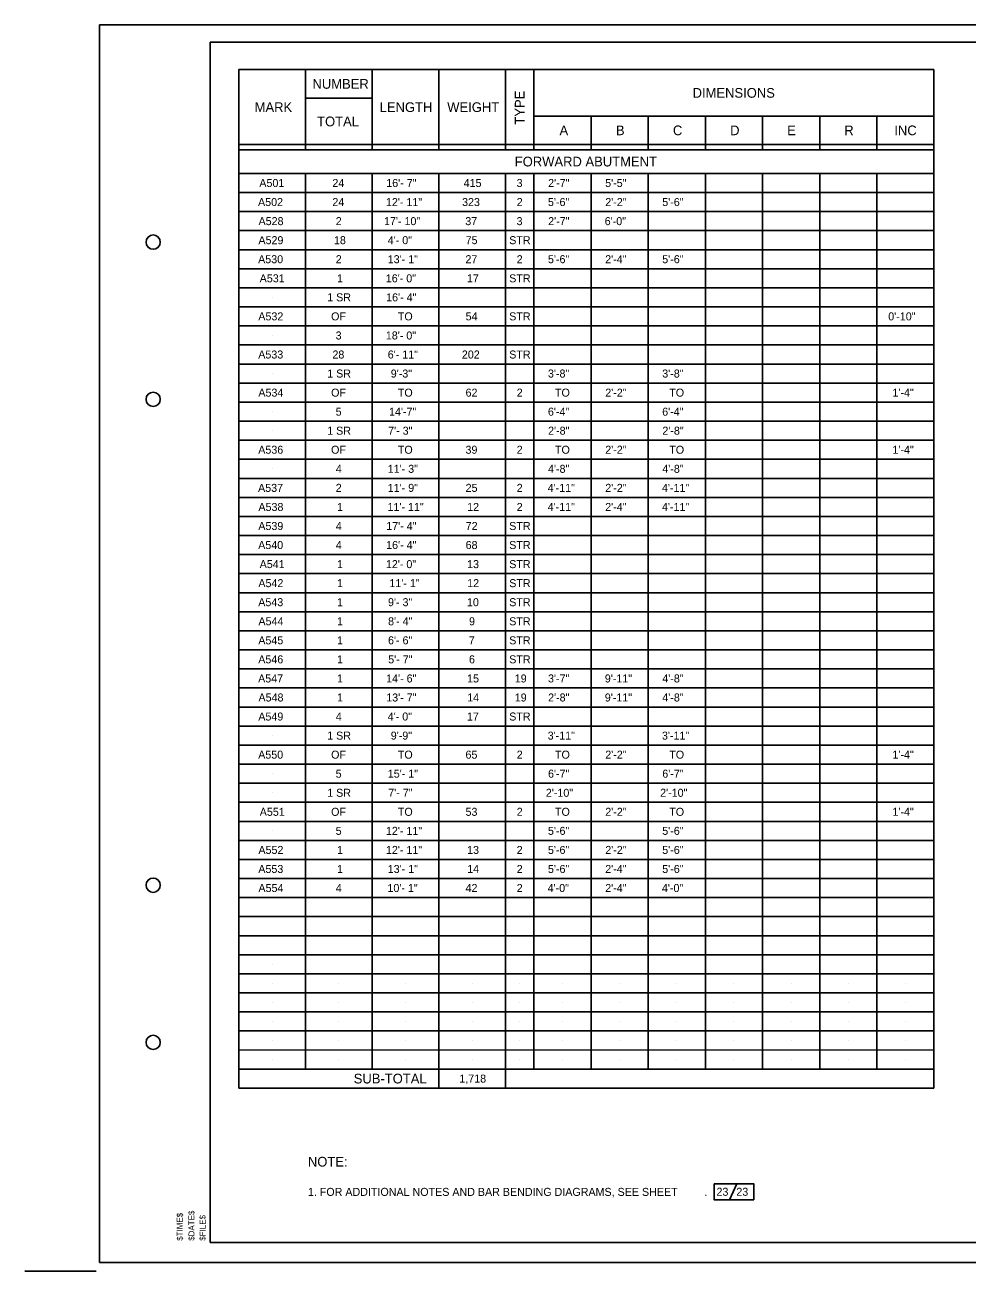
# Model space of a CAD drawing. Extents: x -9.2 to 26.7, y -24.6 to -2.6.
# Drawn here: x -9.21 to 7.28, y -24.61 to -2.81 of the extents above; entities that cross this region are included whole.
import ezdxf

# ---------------------------------------------------------------- set-up
doc = ezdxf.new("R2010")
doc.units = 0
for name, color, linetype in [('BR_P_Gen_Text', 7, 'Continuous'), ('Default', 7, 'Continuous'), ('SC_Scratch1', 7, 'Continuous'), ('SH_Border', 7, 'Continuous'), ('SH_Cut_Line', 7, 'Continuous'), ('TX_P_1', 7, 'Continuous')]:
    doc.layers.add(name, color=color, linetype=linetype)

msp = doc.modelspace()

# ---------------------------------------------------------------- linework, layer by layer
at = {"layer": 'BR_P_Gen_Text'}
for p, q in [((-5.469, -3.594), (6.697, -3.594)), ((-5.469, -21.411), (-5.469, -3.594)), ((-4.302, -4.995), (-4.302, -3.594)), ((-3.135, -4.995), (-3.135, -3.595)), ((-1.969, -4.995), (-1.969, -3.594)), ((-0.802, -4.995), (-0.802, -3.595)), ((-0.302, -4.995), (-0.302, -3.595)), ((6.697, -21.411), (6.697, -3.594)), ((-4.302, -4.094), (-3.135, -4.094)), ((-0.302, -4.407), (6.697, -4.407)), ((0.698, -4.995), (0.698, -4.407)), ((1.698, -4.995), (1.698, -4.407)), ((2.698, -4.995), (2.698, -4.407)), ((3.698, -4.995), (3.698, -4.407)), ((4.698, -4.995), (4.698, -4.407)), ((5.697, -4.995), (5.698, -4.407)), ((-5.469, -4.907), (6.697, -4.907)), ((-5.469, -4.995), (6.697, -4.995)), ((-5.469, -5.411), (6.697, -5.411)), ((-5.469, -5.411), (6.697, -5.411)), ((-4.302, -21.078), (-4.302, -5.411)), ((-3.135, -21.078), (-3.135, -5.411)), ((-1.969, -21.411), (-1.969, -5.411)), ((-0.802, -21.411), (-0.802, -5.411)), ((-0.302, -21.078), (-0.302, -5.411)), ((0.698, -21.078), (0.698, -5.411)), ((1.698, -21.078), (1.698, -5.411)), ((2.698, -21.078), (2.698, -5.411)), ((3.698, -21.078), (3.698, -5.411)), ((4.698, -21.078), (4.698, -5.411)), ((5.698, -21.078), (5.698, -5.411)), ((-5.469, -5.745), (6.697, -5.745)), ((-5.469, -6.078), (6.697, -6.078)), ((-5.469, -6.411), (6.697, -6.411)), ((-5.469, -6.745), (6.697, -6.745)), ((-5.469, -7.078), (6.697, -7.078)), ((-5.469, -7.411), (6.697, -7.411)), ((-5.469, -7.745), (6.697, -7.745)), ((-5.469, -8.078), (6.697, -8.078)), ((-5.469, -8.411), (6.697, -8.411)), ((-5.469, -8.745), (6.697, -8.745)), ((-5.469, -9.078), (6.697, -9.078)), ((-5.469, -9.411), (6.697, -9.411)), ((-5.469, -9.745), (6.697, -9.745)), ((-5.469, -10.078), (6.697, -10.078)), ((-5.469, -10.411), (6.697, -10.411)), ((-5.469, -10.745), (6.697, -10.745)), ((-5.469, -11.078), (6.697, -11.078)), ((-5.469, -11.411), (6.697, -11.411)), ((-5.469, -11.745), (6.697, -11.745)), ((-5.469, -12.078), (6.697, -12.078)), ((-5.469, -12.411), (6.697, -12.411)), ((-5.469, -12.745), (6.697, -12.745)), ((-5.469, -13.078), (6.697, -13.078)), ((-5.469, -13.411), (6.697, -13.411)), ((-5.469, -13.745), (6.697, -13.745)), ((-5.469, -14.078), (6.697, -14.078)), ((-5.469, -14.411), (6.697, -14.411)), ((-5.469, -14.745), (6.697, -14.745)), ((-5.469, -15.078), (6.697, -15.078)), ((-5.469, -15.411), (6.697, -15.411)), ((-5.469, -15.745), (6.697, -15.745)), ((-5.469, -16.078), (6.697, -16.078)), ((-5.469, -16.411), (6.697, -16.411)), ((-5.469, -16.745), (6.697, -16.745)), ((-5.469, -17.078), (6.697, -17.078)), ((-5.469, -17.411), (6.697, -17.411)), ((-5.469, -17.745), (6.697, -17.745)), ((-5.469, -18.078), (6.697, -18.078)), ((-5.469, -18.411), (6.697, -18.411)), ((-5.469, -18.745), (6.697, -18.745)), ((-5.469, -19.078), (6.697, -19.078)), ((-5.469, -19.411), (6.697, -19.411)), ((-5.469, -19.745), (6.697, -19.745)), ((-5.469, -20.078), (6.697, -20.078)), ((-5.469, -20.411), (6.697, -20.411)), ((-5.469, -20.745), (6.697, -20.744)), ((-5.469, -21.078), (6.697, -21.078)), ((-5.469, -21.411), (6.697, -21.411)), ((-5.469, -21.411), (6.697, -21.411))]:
    msp.add_line(p, q, dxfattribs=at)
at = {"layer": 'SC_Scratch1'}
for p, q in [((0.614, -5.203), (0.614, -5.203)), ((-4.885, -5.578), (-4.885, -5.578)), ((-4.885, -5.911), (-4.885, -5.911)), ((-4.885, -6.245), (-4.885, -6.245)), ((-4.885, -6.578), (-4.885, -6.578)), ((-4.885, -6.911), (-4.885, -6.911)), ((-4.885, -7.245), (-4.885, -7.245)), ((-4.885, -7.578), (-4.885, -7.578)), ((-4.885, -7.911), (-4.885, -7.911)), ((-4.885, -8.245), (-4.885, -8.245)), ((-4.885, -8.578), (-4.885, -8.578)), ((-4.885, -8.911), (-4.885, -8.911)), ((-4.885, -9.245), (-4.885, -9.245)), ((-4.885, -9.578), (-4.885, -9.578)), ((-4.885, -9.911), (-4.885, -9.911)), ((-4.885, -9.911), (-4.885, -9.911)), ((-4.885, -10.245), (-4.885, -10.245)), ((-4.885, -10.245), (-4.885, -10.245)), ((-4.885, -10.578), (-4.885, -10.578)), ((-4.885, -10.578), (-4.885, -10.578)), ((-4.885, -10.911), (-4.885, -10.911)), ((-4.885, -11.245), (-4.885, -11.245)), ((-4.885, -11.578), (-4.885, -11.578)), ((-4.885, -11.911), (-4.885, -11.911)), ((-4.885, -12.245), (-4.885, -12.245)), ((-4.885, -12.578), (-4.885, -12.578)), ((-4.885, -12.911), (-4.885, -12.911)), ((-4.885, -13.245), (-4.885, -13.245)), ((-4.885, -13.578), (-4.885, -13.578)), ((-4.885, -13.911), (-4.885, -13.911)), ((-4.885, -14.245), (-4.885, -14.245)), ((-4.885, -14.578), (-4.885, -14.578)), ((-4.885, -14.911), (-4.885, -14.911)), ((-4.885, -15.245), (-4.885, -15.245)), ((-4.885, -15.578), (-4.885, -15.578)), ((-4.885, -15.911), (-4.885, -15.911)), ((-4.885, -16.245), (-4.885, -16.245)), ((-4.885, -16.578), (-4.885, -16.578)), ((-4.885, -16.911), (-4.885, -16.911)), ((-4.885, -17.245), (-4.885, -17.245)), ((-4.885, -17.578), (-4.885, -17.578)), ((-4.885, -17.911), (-4.885, -17.911)), ((-4.885, -19.245), (-4.885, -19.245)), ((-4.885, -19.578), (-4.885, -19.578)), ((-4.885, -19.578), (-4.885, -19.578)), ((-3.719, -19.578), (-3.719, -19.578)), ((-2.552, -19.578), (-2.552, -19.578)), ((-1.385, -19.578), (-1.385, -19.578)), ((-0.552, -19.578), (-0.552, -19.578)), ((0.198, -19.578), (0.198, -19.578)), ((1.198, -19.578), (1.198, -19.578)), ((2.198, -19.578), (2.198, -19.578)), ((3.198, -19.578), (3.198, -19.578)), ((4.198, -19.578), (4.198, -19.578)), ((5.198, -19.578), (5.198, -19.578)), ((6.198, -19.578), (6.198, -19.578)), ((-4.885, -19.911), (-4.885, -19.911)), ((-3.719, -19.911), (-3.719, -19.911)), ((-2.552, -19.911), (-2.552, -19.911)), ((-1.385, -19.911), (-1.385, -19.911)), ((-0.552, -19.911), (-0.552, -19.911)), ((0.198, -19.911), (0.198, -19.911)), ((1.198, -19.911), (1.198, -19.911)), ((2.198, -19.911), (2.198, -19.911)), ((3.198, -19.911), (3.198, -19.911)), ((4.198, -19.911), (4.198, -19.911)), ((5.198, -19.911), (5.198, -19.911)), ((6.197, -19.911), (6.197, -19.911)), ((-4.885, -20.245), (-4.885, -20.245)), ((-3.719, -20.245), (-3.719, -20.245)), ((-2.552, -20.245), (-2.552, -20.245)), ((-1.385, -20.245), (-1.385, -20.245)), ((-0.552, -20.245), (-0.552, -20.245)), ((0.198, -20.245), (0.198, -20.245)), ((1.198, -20.245), (1.198, -20.245)), ((2.198, -20.245), (2.198, -20.245)), ((3.198, -20.245), (3.198, -20.245)), ((4.197, -20.245), (4.197, -20.245)), ((5.197, -20.245), (5.197, -20.245)), ((6.197, -20.245), (6.197, -20.245)), ((-4.885, -20.578), (-4.885, -20.578)), ((-3.719, -20.578), (-3.719, -20.578)), ((-2.552, -20.578), (-2.552, -20.578)), ((-1.386, -20.578), (-1.386, -20.578)), ((-0.552, -20.578), (-0.552, -20.578)), ((0.198, -20.578), (0.198, -20.578)), ((1.198, -20.578), (1.198, -20.578)), ((2.198, -20.578), (2.198, -20.578)), ((3.197, -20.578), (3.197, -20.578)), ((4.197, -20.578), (4.197, -20.578)), ((5.197, -20.578), (5.197, -20.578)), ((6.197, -20.578), (6.197, -20.578)), ((-4.885, -20.911), (-4.885, -20.911)), ((-3.719, -20.911), (-3.719, -20.911)), ((-2.552, -20.911), (-2.552, -20.911)), ((-1.385, -20.911), (-1.385, -20.911)), ((-0.552, -20.911), (-0.552, -20.911)), ((0.198, -20.911), (0.198, -20.911)), ((1.198, -20.911), (1.198, -20.911)), ((2.198, -20.911), (2.198, -20.911)), ((3.198, -20.911), (3.198, -20.911)), ((4.198, -20.911), (4.198, -20.911)), ((5.198, -20.911), (5.198, -20.911)), ((6.198, -20.911), (6.198, -20.911)), ((-2.552, -21.245), (-2.552, -21.245)), ((-1.386, -21.245), (-1.386, -21.245))]:
    msp.add_line(p, q, dxfattribs=at)
at = {"layer": 'SH_Border'}
msp.add_lwpolyline([(-5.966, -3.112), (25.534, -3.112), (25.534, -24.112), (-5.966, -24.112)], close=True, dxfattribs=at)
for centre in [(-6.966, -6.612), (-6.966, -9.362), (-6.966, -17.862), (-6.966, -20.612)]:
    msp.add_circle(centre, 0.125, dxfattribs=at)
at = {"layer": 'SH_Cut_Line'}
msp.add_line((-7.966, -24.612), (-9.21, -24.612), dxfattribs=at)
msp.add_lwpolyline([(26.096, -24.462), (-7.904, -24.462), (-7.904, -2.812), (26.096, -2.812)], close=True, dxfattribs=at)
at = {"layer": 'TX_P_1'}
msp.add_line((3.246, -23.086), (3.117, -23.364), dxfattribs=at)
msp.add_lwpolyline([(2.849, -23.086), (3.545, -23.086), (3.545, -23.364), (2.849, -23.364)], close=True, dxfattribs=at)
msp.add_lwpolyline([(2.849, -23.086), (3.545, -23.086), (3.545, -23.364), (2.849, -23.364)], close=True, dxfattribs=at)

# ---------------------------------------------------------------- texts
at = {"layer": 'BR_P_Gen_Text'}
for s, p in [('A501', (-5.108, -5.648)), ('24', (-3.83, -5.648)), (' 16\'- 7"', (-2.939, -5.648)), ('415', (-1.533, -5.648)), ('3', (-0.606, -5.648)), ('2\'-7"', (-0.054, -5.648)), ('5\'-5"', (0.944, -5.648)), ('A502', (-5.131, -5.981)), ('24', (-3.83, -5.981)), (' 12\'- 11"', (-2.944, -5.981)), ('323', (-1.56, -5.981)), ('2', (-0.604, -5.981)), ('5\'-6"', (-0.057, -5.981)), ('2\'-2"', (0.946, -5.981)), ('5\'-6"', (1.943, -5.981)), ('A528', (-5.122, -6.315)), ('2', (-3.771, -6.315)), (' 17\'- 10"', (-2.978, -6.315)), ('37', (-1.504, -6.315)), ('3', (-0.606, -6.315)), ('2\'-7"', (-0.054, -6.315)), ('6\'-0"', (0.936, -6.315)), ('A529', (-5.124, -6.648)), ('18', (-3.802, -6.648)), (' 4\'- 0"', (-2.913, -6.648)), ('75', (-1.498, -6.648)), ('STR', (-0.735, -6.648)), ('A530', (-5.129, -6.981)), ('2', (-3.771, -6.981)), (' 13\'- 1"', (-2.913, -6.981)), ('27', (-1.501, -6.981)), ('2', (-0.604, -6.981)), ('5\'-6"', (-0.057, -6.981)), ('2\'-4"', (0.945, -6.981)), ('5\'-6"', (1.943, -6.981)), ('A531', (-5.102, -7.315)), ('1', (-3.748, -7.315)), (' 16\'- 0"', (-2.947, -7.315)), ('17', (-1.475, -7.315)), ('STR', (-0.735, -7.315)), ('1 SR', (-3.92, -7.648)), (' 16\'- 4"', (-2.941, -7.648)), ('A532', (-5.126, -7.981)), ('OF', (-3.852, -7.981)), ('TO', (-2.684, -7.981)), ('54', (-1.498, -7.981)), ('STR', (-0.735, -7.981)), ('0\'-10"', (5.898, -7.981)), ('3', (-3.773, -8.315)), (' 18\'- 0"', (-2.946, -8.315)), ('A533', (-5.127, -8.648)), ('28', (-3.829, -8.648)), (' 6\'- 11"', (-2.913, -8.648)), ('202', (-1.564, -8.648)), ('STR', (-0.735, -8.648)), ('1 SR', (-3.92, -8.981)), ('9\'-3"', (-2.808, -8.981)), ('3\'-8"', (-0.057, -8.981)), ('3\'-8"', (1.943, -8.981)), ('A534', (-5.125, -9.315)), ('OF', (-3.852, -9.315)), ('TO', (-2.684, -9.315)), ('62', (-1.499, -9.315)), ('2', (-0.604, -9.315)), ('TO', (0.066, -9.315)), ('2\'-2"', (0.946, -9.315)), ('TO', (2.066, -9.315)), ('1\'-4"', (5.971, -9.315)), ('5', (-3.772, -9.648)), ('14\'-7"', (-2.838, -9.648)), ('6\'-4"', (-0.058, -9.648)), ('6\'-4"', (1.942, -9.648)), ('1 SR', (-3.92, -9.981)), (' 7\'- 3"', (-2.906, -9.981)), ('2\'-8"', (-0.055, -9.981)), ('2\'-8"', (1.945, -9.981)), ('A536', (-5.127, -10.314)), ('OF', (-3.852, -10.314)), ('TO', (-2.684, -10.314)), ('39', (-1.5, -10.314)), ('2', (-0.604, -10.314)), ('TO', (0.066, -10.314)), ('2\'-2"', (0.946, -10.314)), ('TO', (2.066, -10.314)), ('1\'-4"', (5.971, -10.314)), ('4', (-3.77, -10.648)), (' 11\'- 3"', (-2.913, -10.648)), ('4\'-8"', (-0.056, -10.648)), ('4\'-8"', (1.944, -10.648)), ('A537', (-5.13, -10.981)), ('2', (-3.771, -10.981)), (' 11\'- 9"', (-2.913, -10.981)), ('25', (-1.498, -10.981)), ('2', (-0.604, -10.981)), ('4\'-11"', (-0.062, -10.981)), ('2\'-2"', (0.946, -10.981)), ('4\'-11"', (1.938, -10.981)), ('A538', (-5.124, -11.315)), ('1', (-3.748, -11.315)), (' 11\'- 11"', (-2.917, -11.315)), ('12', (-1.471, -11.315)), ('2', (-0.604, -11.315)), ('4\'-11"', (-0.062, -11.315)), ('2\'-4"', (0.945, -11.315)), ('4\'-11"', (1.938, -11.315)), ('A539', (-5.126, -11.648)), ('4', (-3.77, -11.648)), (' 17\'- 4"', (-2.939, -11.648)), ('72', (-1.497, -11.648)), ('STR', (-0.735, -11.648)), ('A540', (-5.128, -11.981)), ('4', (-3.77, -11.981)), (' 16\'- 4"', (-2.941, -11.981)), ('68', (-1.498, -11.981)), ('STR', (-0.735, -11.981)), ('A541', (-5.102, -12.315)), ('1', (-3.748, -12.315)), (' 12\'- 0"', (-2.945, -12.315)), ('13', (-1.472, -12.315)), ('STR', (-0.735, -12.315)), ('A542', (-5.125, -12.648)), ('1', (-3.748, -12.648)), (' 11\'- 1"', (-2.884, -12.648)), ('12', (-1.471, -12.648)), ('STR', (-0.735, -12.648)), ('A543', (-5.127, -12.981)), ('1', (-3.748, -12.981)), (' 9\'- 3"', (-2.908, -12.981)), ('10', (-1.474, -12.981)), ('STR', (-0.735, -12.981)), ('A544', (-5.124, -13.315)), ('1', (-3.748, -13.315)), (' 8\'- 4"', (-2.907, -13.315)), ('9', (-1.438, -13.315)), ('STR', (-0.735, -13.315)), ('A545', (-5.126, -13.648)), ('1', (-3.748, -13.648)), (' 6\'- 6"', (-2.908, -13.648)), ('7', (-1.442, -13.648)), ('STR', (-0.735, -13.648)), ('A546', (-5.127, -13.981)), ('1', (-3.748, -13.981)), (' 5\'- 7"', (-2.905, -13.981)), ('6', (-1.439, -13.981)), ('STR', (-0.735, -13.981)), ('A547', (-5.129, -14.315)), ('1', (-3.748, -14.315)), (' 14\'- 6"', (-2.941, -14.315)), ('15', (-1.472, -14.315)), ('19', (-0.638, -14.315)), ('3\'-7"', (-0.056, -14.315)), ('9\'-11"', (0.938, -14.315)), ('4\'-8"', (1.944, -14.315)), ('A548', (-5.123, -14.648)), ('1', (-3.748, -14.648)), (' 13\'- 7"', (-2.939, -14.648)), ('14', (-1.47, -14.648)), ('19', (-0.638, -14.648)), ('2\'-8"', (-0.055, -14.648)), ('9\'-11"', (0.938, -14.648)), ('4\'-8"', (1.944, -14.648)), ('A549', (-5.126, -14.981)), ('4', (-3.77, -14.981)), (' 4\'- 0"', (-2.913, -14.981)), ('17', (-1.475, -14.981)), ('STR', (-0.735, -14.981)), ('1 SR', (-3.92, -15.315)), ('9\'-9"', (-2.808, -15.315)), ('3\'-11"', (-0.062, -15.315)), ('3\'-11"', (1.938, -15.315)), ('A550', (-5.128, -15.648)), ('OF', (-3.852, -15.648)), ('TO', (-2.684, -15.648)), ('65', (-1.5, -15.648)), ('2', (-0.604, -15.648)), ('TO', (0.066, -15.648)), ('2\'-2"', (0.946, -15.648)), ('TO', (2.066, -15.648)), ('1\'-4"', (5.971, -15.648)), ('5', (-3.772, -15.981)), (' 15\'- 1"', (-2.912, -15.981)), ('6\'-7"', (-0.056, -15.981)), ('6\'-7"', (1.944, -15.981)), ('1 SR', (-3.92, -16.315)), (' 7\'- 7"', (-2.904, -16.315)), ('2\'-10"', (-0.094, -16.315)), ('2\'-10"', (1.906, -16.315)), ('A551', (-5.101, -16.648)), ('OF', (-3.852, -16.648)), ('TO', (-2.684, -16.648)), ('53', (-1.5, -16.648)), ('2', (-0.604, -16.648)), ('TO', (0.066, -16.648)), ('2\'-2"', (0.946, -16.648)), ('TO', (2.066, -16.648)), ('1\'-4"', (5.971, -16.648)), ('5', (-3.772, -16.981)), (' 12\'- 11"', (-2.944, -16.981)), ('5\'-6"', (-0.057, -16.981)), ('5\'-6"', (1.943, -16.981)), ('A552', (-5.124, -17.315)), ('1', (-3.748, -17.315)), (' 12\'- 11"', (-2.944, -17.315)), ('13', (-1.472, -17.315)), ('2', (-0.604, -17.315)), ('5\'-6"', (-0.057, -17.315)), ('2\'-2"', (0.946, -17.315)), ('5\'-6"', (1.943, -17.315)), ('A553', (-5.126, -17.648)), ('1', (-3.748, -17.648)), (' 13\'- 1"', (-2.913, -17.648)), ('14', (-1.47, -17.648)), ('2', (-0.604, -17.648)), ('5\'-6"', (-0.057, -17.648)), ('2\'-4"', (0.945, -17.648)), ('5\'-6"', (1.943, -17.648)), ('A554', (-5.124, -17.981)), ('4', (-3.77, -17.981)), (' 10\'- 1"', (-2.918, -17.981)), ('42', (-1.499, -17.981)), ('2', (-0.604, -17.981)), ('4\'-0"', (-0.063, -17.981)), ('2\'-4"', (0.945, -17.981)), ('4\'-0"', (1.937, -17.981)), ('1,718', (-1.608, -21.315))]:
    msp.add_text(s, height=0.14, dxfattribs=at).set_placement(p)
at = {"layer": 'Default'}
for s, p in [('$TIME$', (-6.448, -24.082)), ('$DATE$', (-6.244, -24.082)), ('$FILE$', (-6.05, -24.082))]:
    msp.add_text(s, height=0.1043, rotation=90.0067, dxfattribs=at).set_placement(p)
at = {"layer": 'TX_P_1'}
for s, rotation, p in [('NUMBER', 0.0002, (-4.178, -3.929)), ('DIMENSIONS', 0.0002, (2.474, -4.086)), ('TYPE', 90.0002, (-0.467, -4.556)), ('MARK', 0.0002, (-5.19, -4.336)), ('LENGTH', 0.0002, (-3.002, -4.336)), ('WEIGHT', 0.0002, (-1.82, -4.336)), ('TOTAL', 0.0002, (-4.097, -4.586)), ('A', 0.0002, (0.145, -4.742)), ('B', 0.0002, (1.132, -4.742)), ('C', 0.0002, (2.13, -4.742)), ('D', 0.0002, (3.131, -4.742)), ('E', 0.0002, (4.129, -4.742)), ('R', 0.0002, (5.129, -4.742)), ('INC', 0.0002, (6.004, -4.742)), ('FORWARD ABUTMENT', 0.0002, (-0.638, -5.288))]:
    msp.add_text(s, height=0.17, rotation=rotation, dxfattribs=at).set_placement(p)
for s, height, p in [('SUB-TOTAL', 0.17, (-3.456, -21.33)), ('NOTE:', 0.17, (-4.258, -22.784)), ('1. FOR ADDITIONAL NOTES AND BAR BENDING DIAGRAMS, SEE SHEET         .', 0.14, (-4.258, -23.297)), ('23', 0.14, (2.892, -23.295)), ('23', 0.14, (3.24, -23.295))]:
    msp.add_text(s, height=height, dxfattribs=at).set_placement(p)

doc.saveas('drawing.dxf')
